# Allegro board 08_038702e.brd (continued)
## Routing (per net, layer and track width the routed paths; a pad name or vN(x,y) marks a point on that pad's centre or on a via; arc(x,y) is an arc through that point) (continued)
PS_MIO41_501_SD0_CMD: length 53.3
  TOP w0.14: U11.4 10.36,14.84 10.93,14.26 16.87,14.26 17.07,14.46 v1(17.07,14.84) ; U1.C19 v1(45.22,24.59)
  L17_SIG w0.095: v1(45.22,24.59) 45.22,24.57 44.63,23.98 43.34,23.98 40.29,27.03 33.11,27.03 32.85,27.29 32.85,27.38 32.55,27.68 32.55,27.73 32.36,27.93 32.3,27.93 31.65,28.58 31.65,30.04 31.49,30.21 25.33,30.21 24.56,29.44 24.56,22.45 21.36,19.25 21.22,19.25 19.27,17.29 19.27,16.02 19.23,15.98 19.23,14.97 18.34,14.08 17.71,14.08 17.6,14.18 17.35,14.18 17.07,14.46 v1(17.07,14.84)
PS_MIO42_501_SD0_DATA0: length 48.7
  TOP w0.14: U1.F17 v1(42.22,26.59) ; v1(10.47,16.11) 10.19,15.84 U11.6
  L17_SIG w0.095: v1(10.47,16.11) 10.72,16.36 11.61,16.36 12.5,15.48 15.04,15.48 15.29,15.73 15.29,16.49 15.8,17 16.44,17 19.27,19.83 19.27,20.12 21.07,21.93 21.36,21.93 21.88,22.45 21.88,22.73 22.07,22.93 22.36,22.93 22.88,23.45 22.88,30.81 23.32,31.25 23.36,31.25 23.56,31.45 23.56,31.49 24.06,31.99 31.42,31.99 31.88,31.53 31.88,31.45 32.07,31.25 32.16,31.25 33.49,29.91 33.97,29.91 34.17,29.71 34.17,29.23 34.48,28.93 40.36,28.93 40.56,28.73 40.56,28.45 41.07,27.93 41.36,27.93 41.56,27.73 41.56,27.44 42.22,26.78 v1(42.22,26.59)
PS_MIO43_501_SD0_DATA1: length 51.2
  TOP w0.14: v1(9.7,17.76) 9.05,17.11 U11.7 ; U1.D18 v1(44.22,25.59)
  L17_SIG w0.095: v1(9.7,17.76) 14.4,17.76 15.8,19.16 17.83,19.16 20.5,21.83 20.5,29.57 21.18,30.25 21.36,30.25 23.56,32.45 23.56,32.63 24.06,33.13 31.09,33.13 31.29,32.93 31.36,32.93 32.55,31.73 32.55,31.67 35.07,29.15 40.45,29.15 40.78,28.82 40.78,28.54 41.17,28.15 41.45,28.15 41.78,27.82 41.78,27.53 42.56,26.75 42.56,26.69 43,26.25 43.56,26.25 v1(44.22,25.59)
PS_MIO44_501_SD0_DATA2: length 50
  TOP w0.14: U1.E18 v1(43.22,25.59) ; v1(10.59,13.06) 10.32,13.34 U11.1
  L17_SIG w0.095: v1(10.59,13.06) 10.89,13.36 12.29,13.36 13.77,14.84 15.93,14.84 16.31,15.22 17.58,15.22 18.98,16.62 18.98,17.89 19.27,18.18 19.27,18.54 19.47,18.74 19.82,18.74 20.12,19.03 20.37,19.03 20.88,19.53 20.88,19.73 23.07,21.93 23.27,21.93 23.88,22.53 23.88,29.73 25.12,30.97 31.04,30.97 31.88,30.13 31.88,29.45 32.55,28.77 32.55,28.57 33.19,27.93 40.36,27.93 40.56,27.73 40.56,27.45 41.07,26.93 41.36,26.93 41.56,26.73 41.56,26.45 42.07,25.93 42.36,25.93 42.7,25.59 v1(43.22,25.59)
PS_MIO45_501_SD0_DATA3: length 52.2
  TOP w0.14: U11.3 10.34,14.34 v1(10.97,13.7) ; U1.C18 v1(45.22,25.59)
  L17_SIG w0.095: v1(45.22,25.59) 45.22,25.59 44.63,25 44.12,25 43.61,25.51 43.61,25.76 43.36,26.02 42.6,26.02 42.37,26.25 42.07,26.25 41.88,26.45 41.88,26.74 41.46,27.15 41.17,27.15 40.78,27.54 40.78,27.82 40.45,28.15 34.17,28.15 32.88,29.45 32.88,29.61 31.29,31.19 24.34,31.19 23.88,30.73 23.88,30.66 23.55,30.33 23.55,29.74 23.56,29.73 23.56,23.13 23.36,22.93 23.07,22.93 22.88,22.73 22.88,22.45 22.36,21.93 22.07,21.93 21.88,21.73 21.88,21.45 21.36,20.93 21.07,20.93 20.88,20.73 20.88,20.3 20.5,19.92 20.12,19.92 18.59,18.4 18.47,18.4 16.44,16.36 16.44,15.82 15.67,15.06 13.68,15.06 12.31,13.7 v1(10.97,13.7)
PS_MIO46_501_JX4: length 50.9
  TOP w0.14: U1.E17 v1(43.22,26.59)
  L17_SIG w0.095: v1(78.79,16.24) 78.41,16.62 77.52,16.62 77.14,17 77.14,19.03 76.76,19.41 75.87,19.41 75.49,19.03 75.49,18.02 75.11,17.63 74.47,17.63 74.09,18.02 74.09,22.84 71.68,25.25 58.38,25.25 57.84,24.71 50,24.71 47.68,27.03 43.61,27.03 43.22,26.63 v1(43.22,26.59)
  BOTTOM w0.14: JX4.92 80.46,14.57 v1(78.79,16.24)
PS_MIO47_501_JX4: length 49.1
  TOP w0.14: U1.B19 v1(46.22,24.59)
  L17_SIG w0.095: v1(46.22,24.59) 46.69,24.11 49.2,24.11 49.46,23.86 58.47,23.86 59.11,24.49 59.87,24.49 60.12,24.24 60.89,24.24 61.39,24.75 65.58,24.75 65.84,24.49 71.93,24.49 73.71,22.71 73.71,19.29 73.2,18.78 73.2,17.13 73.59,16.75 75.49,16.75 75.87,17.13 75.87,18.52 76.13,18.78 76.5,18.78 76.76,18.52 76.76,16.49 77.14,16.11 v1(77.78,16.11)
  BOTTOM w0.14: v1(77.78,16.11) 79.81,14.08 80.44,14.08 80.75,13.77 JX4.94
PS_MIO48_501_JX4: length 47.2
  TOP w0.14: U1.B21 v1(46.22,22.59)
  L6_SIG w0.095: v1(46.22,22.59) 46.72,22.08 47.8,22.08 48.06,22.33 48.31,22.33 49.2,21.44 50.44,21.44 50.45,21.45 52.33,21.45 52.34,21.44 54.28,21.44 55.04,20.68 57.33,20.68 58.09,19.92 73.84,19.92 75.87,17.89 78.54,17.89 79.05,17.38 80.32,17.38 81.46,16.24 81.46,12.94 82.98,11.41 v1(84.38,11.41)
  BOTTOM w0.14: v1(84.38,11.41) 84.42,11.37 JX4.99
PS_MIO49_501_JX4: length 51.3
  TOP w0.14: U1.A18 v1(47.22,25.59)
  L6_SIG w0.095: v1(47.22,25.59) 46.66,25.03 46.66,23.6 47.17,23.1 47.8,23.1 48.19,22.71 48.57,22.71 49.03,22.25 52.33,22.25 52.76,21.83 54.66,21.83 54.92,21.57 57.58,21.57 58.85,20.3 60.25,20.3 60.5,20.56 61.14,20.56 61.39,20.3 68,20.3 68.51,20.81 69.78,20.81 70.28,20.3 74.6,20.3 76.76,18.14 78.98,18.14 79.13,18.29 79.47,18.29 79.62,18.14 82.71,18.14 82.71,18.13 82.91,17.93 83.19,17.93 83.28,18.03 83.48,18.03 83.75,17.76 83.75,13.06 83.49,12.81 v1(83.49,11.92)
  BOTTOM w0.14: JX4.98 81.55,12.17 83.24,12.17 v1(83.49,11.92)
PS_MIO50_501_SD0_CD: length 72.7
  TOP w0.14: v1(77.9,59.16) 77.9,58.66 78.08,58.47 U5.8 ; U1.B22 v1(46.22,21.59)
  L15_SIG w0.095: v3(70.41,21.19) 70.41,22.21 73.84,25.64 73.84,31.73 70.66,34.91 70.66,37.83 72.57,39.73 72.57,50.02 73.97,51.42 73.97,52.31 75.87,54.21 76.76,54.21 78.67,56.12 78.67,58.4 v1(77.9,59.16)
  L17_SIG w0.095: v3(70.41,21.19) 69.9,20.68 65.84,20.68 65.2,20.05 61.39,20.05 58.98,22.46 49.33,22.46 49.07,22.21 46.79,22.21 46.22,21.63 v1(46.22,21.59)
PS_MIO51_501_JX4: length 49.1
  TOP w0.14: U1.B20 v1(46.22,23.59)
  L6_SIG w0.095: v1(46.22,23.59) 46.22,23.54 45.77,23.1 45.01,23.1 44.76,22.84 44.76,21.44 45.14,21.06 46.28,21.06 46.88,20.47 46.88,20.45 47.07,20.25 48.11,20.25 48.44,19.92 57.46,19.92 59.23,18.14 60.12,18.14 60.76,18.78 70.28,18.78 70.54,18.52 70.92,18.52 74.09,15.35 74.09,14.33 77.9,10.52 82.35,10.52 v1(82.73,10.9)
  BOTTOM w0.14: JX4.100 82.26,11.37 v1(82.73,10.9)
PS_MIO52_501_ETH0_MDC: length 52.2
  TOP w0.14: U1.A20 v1(47.22,23.59)
  L17_SIG w0.095: v1(25.96,2.78) 26.34,2.78 26.47,2.65 28.25,2.65 29.01,3.41 33.45,3.41 35.1,5.06 40.18,5.06 40.69,5.57 46.03,5.57 v3(46.79,6.33)
  L18_SIG w0.095: v3(46.79,6.33) 49.33,8.87 49.33,9.63 50.73,11.03 50.73,13.7 50.47,13.95 50.47,15.22 50.98,15.73 50.98,20.41 50.73,20.65 50.57,20.65 49.45,21.77 49.45,21.95 47.82,23.59 v1(47.22,23.59) ; v1(21.13,1.12) 22.79,2.78 25.3,2.78 25.31,2.77 25.59,2.77 25.6,2.78 v1(25.96,2.78)
  BOTTOM w0.14: U10.7 21.89,2.86 21.66,2.63 21.66,1.65 v1(21.13,1.12)
PS_MIO53_501_ETH0_MDIO: length 51.7
  TOP w0.14: U1.A19 v1(47.22,24.59)
  L17_SIG w0.095: v3(45.65,6.33) 45.14,5.82 40.44,5.82 40.18,5.57 32.95,5.57 31.8,4.43 31.17,4.43 30.53,3.79 28.63,3.79 27.99,4.43 v1(27.36,4.43)
  L18_SIG w0.095: v3(45.65,6.33) 46.92,7.6 47.3,7.6 48.06,8.36 48.06,10.65 48.95,11.54 48.95,13.57 49.33,13.95 49.33,17.63 49.2,17.76 49.2,21.19 47.3,23.1 47.04,23.1 46.79,23.35 46.79,24.16 v1(47.22,24.59) ; v1(21.01,1.63) 23.42,4.05 26.98,4.05 v1(27.36,4.43)
  BOTTOM w0.14: R11.2 27.74,4.05 v1(27.36,4.43) ; v1(21.01,1.63) 21.01,2.39 21.39,2.78 U10.8
PWR_ENABLE: length 135.2
  TOP w0.14: v1(31.93,57.64) 31.55,57.26 30.41,57.26 29.8,56.66 29.8,56.54 29.45,56.19 R56.2 ; v2(58.35,11.28) 58.47,11.28 58.75,11.01 U4.12 ; U18.20 25.57,5.71 25.83,5.44 25.83,4.05 25.45,3.66 v1(25.45,3.11)
  L2_GND w0.203: v2(58.35,11.28) v3(57.96,11.28)
  L3_SIG w0.095: v3(57.96,11.28) 58.28,11.6 58.41,11.6 58.6,11.41 59.11,11.41 59.38,11.69 59.38,11.69 59.74,12.05 59.74,12.9 60.12,13.28 60.12,14.33 59.28,15.18 59.28,17.29 60.38,18.4 60.38,19.03 60.12,19.29 60.12,22.33 59,23.46 59,24.89 59.36,25.25 59.36,29.06 59.23,29.19 v1(59.23,30.21)
  L7_SIG w0.095: v3(57.96,11.28) 57.08,11.28 56.06,10.27 56.06,3.03 53.9,0.87 35.36,0.87 34.09,2.14 34.09,4.43 33.07,5.44 31.29,5.44 30.66,4.81 29.64,4.81 27.27,2.44 25.79,2.44 25.45,2.78 v1(25.45,3.11)
  L17_SIG w0.095: v3(49.07,30.84) 53.93,30.84 54.14,31.06 54.42,31.06 54.63,30.84 57.46,30.84 58.43,29.87 58.87,29.87 59.21,30.21 v1(59.23,30.21)
  L18_SIG w0.095: v3(49.07,30.84) 48.82,31.1 43.99,31.1 43.61,31.48 43.61,34.78 43.36,35.03 42.09,35.03 41.71,35.41 41.71,43.92 41.33,44.3 41.33,46.84 41.84,47.35 41.84,52.56 40.69,53.7 40.69,54.46 41.33,55.1 41.33,57 39.04,59.29 32.69,59.29 31.93,58.53 v1(31.93,57.64)
  BOTTOM w0.14: JX1.5 32.73,56.84 v1(31.93,57.64)
PWR_GD: length 172
  TOP w0.203: U7.37 v1(5.91,42.03)
  TOP w0.254: v1(42.34,53.83) 41.96,53.44 U9.7
  TOP w0.305: U19.5 71.13,7.77 v1(71.55,7.35) ; R306.1 v1(72.82,7.35)
  TOP w0.381: U20.5 80.91,7.77 v1(81.21,7.47)
  L9_POWER w0.508: v1(81.21,7.47) 80.82,7.09 76.89,7.09 75.02,5.23 74.31,5.23 72.82,6.71 v1(72.82,7.35) v1(71.55,7.35)
  L17_SIG w0.508: v1(81.21,7.47) 81.84,6.84 86.16,6.84 88.57,9.25 88.57,34.4 89.84,35.67 89.84,43.8 88.57,45.07 88.57,51.04 84.25,55.35 78.03,55.35 77.9,55.23 73.59,55.23 73.08,54.72 71.43,54.72 70.66,55.48 43.11,55.48 42.34,54.72 ; v1(5.91,42.03) 6.53,42.65 6.53,44.05 5.39,45.19 5.39,51.42 11.61,57.64 14.4,57.64 15.29,58.53 21.64,58.53 22.59,57.58 25.78,57.58 26.34,58.15 28.37,58.15 29.26,59.04 35.36,59.04 36.5,57.89 36.5,56.24 37.26,55.48 41.58,55.48 42.34,54.72 ; 42.34,54.72 v1(42.34,53.83)
PWR_GD_1.35V: length 86.5
  TOP w0.102: v1(25.92,3.32) 25.92,3.37 26.09,3.54 26.09,5.95 25.83,6.21 U18.21
  TOP w0.203: U1.C23 v1(45.22,20.59)
  TOP w0.254: R3.2 41.58,4.3 v1(41.07,4.81) ; v1(40.57,4.81) 40.31,4.81 39.93,5.19 SW1.1A
  TOP w0.305: U4.2 62.42,8.12 62.59,7.96 62.65,7.96 v1(62.68,7.92) ; v2(62.28,10.65) 62.28,10.27 62.14,10.12 U4.6
  TOP w0.508: SW1.1B SW1.1A
  L2_GND w0.305: v2(62.28,10.65) v3(62.79,10.65)
  L3_SIG w0.254: v1(61.65,13.44) 61.9,13.44 62.54,12.81 62.54,10.9 v3(62.79,10.65) 62.68,10.54 v1(62.68,7.92) 61.84,7.92 60.5,6.59 59.36,6.59 55.93,3.16 54.66,3.16 53.68,4.14 50.63,4.14 49.67,5.1 44.92,5.1 43.81,3.99 41.25,3.99 41.07,4.17 v1(41.07,4.81) v1(40.57,4.81)
  L11_POWER w0.254: v1(61.65,13.44) 60.38,14.71 55.55,14.71 53.39,16.87 53.39,21.83 52.63,22.59 49.46,22.59 47.93,21.06 45.69,21.06 v1(45.22,20.59)
  L14_SIG w0.254: v1(25.92,3.32) 26.3,3.32 26.72,2.9 30.41,2.9 31.42,3.92 34.34,3.92 35.23,4.81 v1(40.57,4.81) v1(41.07,4.81)
  BOTTOM w0.305: R29.2 61.01,13.7 61.06,13.65 61.31,13.65 61.52,13.44 v1(61.65,13.44)
REF_IN_OUT: length 5.3
  TOP w0.14: U7.13 v1(14.13,41.53) 14.13,41.66 13.76,42.03 U7.14
  BOTTOM w0.14: C202.1 14.53,40.75 14.28,41 14.28,41.38 v1(14.13,41.53)
RX1A_N: length 2.5
  TOP w0.089: U17.M2 68.96,34.09 69.09,34.22 69.09,34.73 70.03,35.67 70.03,35.8 C8.2
RX1A_P: length 2.5
  TOP w0.089: U17.M1 69.48,34.09 69.31,34.27 69.31,34.64 70.11,35.44 C9.2
RX1B_N: length 3.6
  TOP w0.089: U17.J1 69.89,31.4 70.06,31.4 70.18,31.52 70.2,31.52 70.28,31.6 70.28,32.75 70.41,32.87 70.41,33.13 70.66,33.38 71.11,33.38 C51.2
RX1B_P: length 3.6
  TOP w0.089: U17.H1 69.89,31.19 70.15,31.19 70.27,31.31 70.29,31.31 70.5,31.51 70.5,32.66 70.63,32.78 70.63,33.04 70.75,33.17 71.06,33.17 C52.2
RX2A_N: length 2.9
  TOP w0.089: U17.A1 69.33,25.29 69.29,25.26 69.29,25.13 69.36,25.07 69.36,24.91 69.52,24.75 70.79,24.75 70.92,24.62 70.93,24.63 C10.2
RX2A_P: length 2.8
  TOP w0.089: C11.2 70.82,24.4 70.83,24.4 70.7,24.53 69.43,24.53 69.14,24.82 69.14,24.98 68.83,25.29 U17.A2
RX2B_N: length 2.8
  TOP w0.089: C53.2 71.32,27.88 70.88,27.88 70.63,28.14 70.63,28.65 70.27,29 69.89,29 U17.F1
RX2B_P: length 2.9
  TOP w0.089: U17.E1 69.89,28.79 70.18,28.79 70.41,28.56 70.41,28.05 70.79,27.67 71.22,27.67 C56.2
S_IN_N: length 57.1
  L17_SIG w0.089: v1(6.53,7.28) 6.74,7.49 9.18,7.49 11.61,5.06 18.85,5.06 19.61,4.3 19.61,3.66 20.25,3.03 21.13,3.03 22.28,4.17 23.8,4.17 24.06,3.92 24.06,3.41 24.44,3.03 24.44,2.39 24.33,2.29 v1(24.33,2.01)
  BOTTOM w0.089: U10.2 24.39,2.6 24.53,2.46 24.53,2.22 v1(24.33,2.01) ; v1(6.53,7.28) 6.29,7.51 5.48,7.51 4.62,8.36 2.59,8.36 1.58,9.38 1.58,23.1 0.9,23.77 0.9,32.2 2.27,33.57 3.54,33.57 3.79,33.81 JP2.3
S_IN_P: length 57.1
  L17_SIG w0.089: v1(6.53,7.96) 6.74,7.75 9.28,7.75 11.71,5.32 18.95,5.32 19.86,4.4 19.86,3.77 20.35,3.28 21.03,3.28 22.17,4.43 23.91,4.43 24.31,4.02 24.31,3.52 24.69,3.13 24.69,2.97 24.82,2.84 24.82,2.65 24.69,2.52 24.69,2.14 24.82,2.01 v1(25.01,2.01)
  BOTTOM w0.089: U10.1 24.89,2.6 24.75,2.46 24.75,2.28 v1(25.01,2.01) ; JP1.3 3.79,33.22 3.65,33.36 2.36,33.36 1.11,32.11 1.11,23.86 1.79,23.19 1.79,9.47 2.68,8.58 4.71,8.58 5.56,7.73 6.29,7.73 v1(6.53,7.96)
S_OUT_N: length 56.4
  L7_SIG w0.089: v1(17.96,32.49) 17.96,32.37 17.71,32.11 16.94,32.11 15.42,33.64 9.32,33.64 7.42,31.73 7.42,29.06 9.2,27.29 11.86,27.29 13.96,25.19 13.96,21.45 13.69,21.18 13.69,20.69 14.15,20.23 14.15,19.67 14.53,19.29 14.53,18.78 13.54,17.79 13.54,17.22 13.43,17.12 13.43,16.12 13.54,16.01 13.54,13.93 15.04,12.43 15.04,11.03 15.8,10.27 16.69,10.27 17.71,9.25 17.71,6.33 19.61,4.43 19.61,3.66 20.84,2.44 22.89,2.44 23.04,2.29 23.04,2.01 v1(22.79,1.76)
  BOTTOM w0.089: v1(22.79,1.76) 23.03,2.01 23.03,2.46 22.89,2.6 U10.5 ; JP4.3 17.15,32.29 17.39,32.05 17.51,32.05 v1(17.96,32.49)
S_OUT_P: length 56.4
  L7_SIG w0.089: v1(17.96,31.73) 17.83,31.86 16.84,31.86 15.31,33.38 9.43,33.38 7.67,31.63 7.67,29.17 9.3,27.54 11.97,27.54 14.21,25.3 14.21,21.35 13.94,21.08 13.94,20.8 14.4,20.33 14.4,19.77 14.78,19.39 14.78,18.67 13.79,17.68 13.79,17.12 13.69,17.01 13.69,16.23 13.79,16.12 13.79,14.03 15.29,12.53 15.29,11.14 15.91,10.52 16.79,10.52 17.96,9.36 17.96,6.44 19.86,4.53 19.86,3.77 20.94,2.69 22.99,2.69 23.29,2.39 23.29,2.01 v1(23.55,1.76)
  BOTTOM w0.089: JP3.3 17.07,30.79 17.07,31.6 17.3,31.83 17.6,31.83 17.79,32.02 17.92,32.02 17.98,31.96 17.98,31.76 v1(17.96,31.73) ; U10.4 23.39,2.6 23.25,2.46 23.25,2.06 v1(23.55,1.76)
SCL: length 69.5
  TOP w0.14: U1.AF24 v1(21.22,19.59)
  L14_SIG w0.095: v1(37.85,8.52) 37.7,8.36 37.52,8.36 36.88,7.73 36.88,7.6 35.96,6.68 29.36,6.68 28.75,6.08 27.36,6.08 27.1,6.33 26.34,6.33 24.69,4.68 22.02,4.68 21.32,5.38 20.82,5.38 20.37,5.82 19.86,5.82 19.48,5.44 18.72,5.44 17.71,6.46 17.71,10.9 17.03,11.58 15.63,11.58 15.29,11.92 15.29,14.08 16.44,15.22 17.58,15.22 17.83,15.48 17.83,15.98 17.32,16.49 17.32,17.38 17.71,17.76 20.5,17.76 20.75,18.02 21.39,18.02 21.64,18.27 21.64,18.78 21.22,19.2 v1(21.22,19.59) 20.17,19.59 19.86,19.29 18.21,19.29 16.94,20.56 14.15,20.56 12.75,21.95 11.1,21.95 9.96,23.1 7.49,23.1 4.31,19.92 4.31,19.41 v1(4.24,19.34)
  BOTTOM w0.14: R58.2 v1(4.24,19.34) 4.31,19.41 U21.2 ; JX2.17 37.53,9.12 37.77,8.87 37.77,8.59 v1(37.85,8.52)
SCL_ADM1166: length 182.3
  TOP w0.14: U7.35 v1(5.9,43.03)
  L4_SIG w0.095: v1(4.23,42.78) 4.75,42.78 5.01,43.03 5.89,43.03 v1(5.9,43.03) 6.53,42.4 6.53,41.51 4.88,39.86 4.88,32.49 5.77,31.6 5.77,25.38 v1(6.15,25)
  L14_SIG w0.095: v1(6.15,25) 6.78,25 7.29,25.51 11.61,25.51 12.63,24.49 16.18,24.49 18.72,21.95 21.37,21.95 22.07,21.25 22.22,21.25 22.79,20.68 22.79,19.54 22.88,19.45 23.07,19.25 23.58,19.25 23.88,18.96 23.88,16.1 24.82,15.15 24.82,14.33 25.96,13.19 30.53,13.19 32.06,11.67 36.88,11.67 37.39,12.17 v3(37.39,12.55)
  L17_SIG w0.095: v3(37.39,12.55) 39.42,10.52 48.19,10.52 49.58,9.13 50.34,9.13 52.12,7.35 63.93,7.35 65.2,6.08 72.44,6.08 72.82,5.7 75.49,5.7 76.38,6.59 78.54,6.59 82.09,10.14 85.02,10.14 86.29,11.41 86.29,33.26 88.32,35.29 88.32,41.89 v1(87.43,42.78) 85.9,41.26 85.9,40.37 85.02,39.48 83.24,39.48 80.95,41.76 80.95,43.29 77.78,46.46 v3(77.78,47.61)
  L19_GND w0.203: v4(77.27,47.61) v3(77.78,47.61)
  BOTTOM w0.14: R51.2 v1(4.23,42.78) ; v1(6.15,25) 5.64,24.49 4.62,24.49 4.31,24.8 U21.7 ; P1.A4 v1(87.43,42.78) ; U24.15 77.13,47.46 v4(77.27,47.61)
  BOTTOM w0.381: P1.B4 94.41,42.78 93.78,42.15 91.87,42.15 91.24,42.78 P1.A4
SD_SEL: length 147.5
  TOP w0.14: U5.5 v2(79.68,57.51) ; U11.24 9.05,12.66 9.2,12.81 10.21,12.81 v1(10.59,12.43) ; S1.2 v1(2.89,11.71)
  L2_GND w0.305: v2(79.68,57.51) v3(79.17,57.51)
  L14_SIG w0.095: v3(79.17,57.51) 79.81,58.15 79.81,60.43 79.05,61.2 51.11,61.2 50.73,60.81 48.69,60.81 48.31,60.43 47.1,60.43 47.08,60.41 46.75,60.41 46.73,60.43 44.38,60.43 43.93,60.88 33.39,60.88 31.93,59.42 28.12,59.42 27.61,59.93 22.28,59.93 20.75,58.4 20.75,54.97 19.1,53.32 15.67,53.32 12.75,50.4 12.75,46.84 11.61,45.7 9.2,45.7 7.67,44.18 4.62,44.18 2.85,42.4 2.85,41.64 0.56,39.35 0.56,16.24 3.61,13.19 9.83,13.19 v1(10.59,12.43)
  L17_SIG w0.095: v1(2.89,11.71) 5.47,11.71 5.77,11.41 8.05,11.41 9.32,12.68 10.34,12.68 v1(10.59,12.43)
  BOTTOM w0.14: v1(11.99,9.63) 11.99,10.14 10.59,11.54 v1(10.59,12.43)
SDA: length 69
  TOP w0.14: U1.AF25 v1(21.22,18.59)
  L14_SIG w0.095: v1(39.14,9) 39.14,8.97 38.79,8.62 38.79,7.98 38.15,7.35 37.01,7.35 36.12,6.46 29.9,6.46 29.26,5.82 27.61,5.82 27.36,5.57 25.96,5.57 24.82,4.43 21.9,4.43 21.39,4.93 20.2,4.93 19.95,5.19 18.47,5.19 17.32,6.33 17.32,10.78 16.74,11.36 15.47,11.36 15.04,11.79 15.04,14.21 16.44,15.6 16.44,16.24 17.07,16.87 17.07,17.63 17.45,18.02 20.37,18.02 20.59,18.24 21.13,18.24 21.22,18.32 v1(21.22,18.59) 20.31,18.59 19.91,18.99 17.11,18.99 16.56,19.54 14.4,19.54 13.64,20.3 5.77,20.3 4.37,18.9 3.86,18.9 3.48,19.29 v1(3.1,19.29)
  BOTTOM w0.14: v1(39.14,9) 38.58,9 38.33,9.25 JX2.19 ; U21.3 3.66,19.85 v1(3.1,19.29) 2.59,19.29 R57.2
SDA_ADM1166: length 179.8
  TOP w0.14: U7.36 v1(5.26,42.53)
  L4_SIG w0.095: v1(6.15,23.98) 5.39,24.75 5.39,31.22 4.5,32.11 4.5,40.62 4.24,40.88 v1(4.24,42.02) 4.75,42.02 v1(5.26,42.53)
  L14_SIG w0.095: v1(6.15,23.98) 6.66,24.49 11.1,24.49 11.74,23.86 15.17,23.86 16.56,22.46 16.94,22.46 18.34,21.06 21.39,21.06 21.77,20.68 21.77,19.41 22.15,19.03 22.98,19.03 22.98,19.03 23.29,19.03 23.55,18.77 23.55,17.45 23.55,17.44 23.55,16.11 23.93,15.73 23.93,13.95 25.96,11.92 29.9,11.92 30.53,11.28 37.01,11.28 38.15,12.43 v3(38.15,12.81)
  L17_SIG w0.095: v3(76.13,47.86) 76.13,44.69 79.43,41.38 80.32,41.38 82.73,38.97 85.9,38.97 v1(87.68,37.19) 85.9,35.41 85.9,11.67 84.63,10.4 81.97,10.4 78.54,6.97 72.57,6.97 72.19,6.59 68.38,6.59 66.47,8.49 64.95,8.49 63.45,9.99 56.29,9.99 55.42,9.13 51.23,9.13 50.85,9.51 49.92,9.51 48.4,11.03 39.93,11.03 v3(38.15,12.81)
  L19_GND w0.203: v3(76.13,47.86) 76.39,47.6 v4(76.63,47.6)
  BOTTOM w0.14: v1(6.15,23.98) 4.24,23.98 3.66,24.56 U21.6 ; P1.A3 88.95,40.24 87.94,39.22 87.94,37.45 v1(87.68,37.19) ; R52.2 v1(4.24,42.02) ; U24.14 v4(76.63,47.6)
  BOTTOM w0.381: P1.A3 P1.B3
SDIO_CLKB0: length 26.1
  TOP w0.14: v1(1.45,28.81) 2.08,28.81 2.54,28.36 J3.5 ; U11.19 6.55,12.19 v1(6.15,11.79)
  L3_SIG w0.095: v1(1.45,28.81) 1.96,28.81 2.37,28.4 2.37,28.34 4.12,26.59 4.12,20.81 4.75,20.17 4.75,18.9 4.12,18.27 4.12,16.87 3.61,16.36 2.72,16.36 2.08,15.73 2.08,15.35 1.7,14.97 1.7,14.71 4.62,11.79 v1(6.15,11.79)
SDIO_CLKB1: length 17
  TOP w0.14: v1(5.64,17) 5.04,16.4 5.04,16.2 5.41,15.84 U11.13
  L3_SIG w0.095: v1(5.64,17) 7.29,17 7.93,17.63 7.93,26.65 v1(9.45,28.17)
  BOTTOM w0.14: JX3.43 v1(9.45,28.17)
SDIO_CMDB0: length 22.2
  TOP w0.14: U11.20 7.05,12.06 v1(5.89,10.9) ; J3.3 v1(1.85,26.16)
  L3_SIG w0.095: v1(5.89,10.9) 5.13,10.9 1.07,14.97 1.07,18.52 1.45,18.9 1.45,25.76 v1(1.85,26.16)
  BOTTOM w0.14: v1(5.89,10.9) R109.2
SDIO_CMDB1: length 13.7
  TOP w0.14: v1(5.77,17.76) 6.55,16.98 U11.12
  L15_SIG w0.095: v1(5.77,17.76) 6.28,18.27 8.18,18.27 10.97,21.06 10.97,22.08 10.59,22.46 v1(10.59,23.35)
  BOTTOM w0.14: JX3.34 11.41,24.17 10.8,23.56 10.8,23.56 v1(10.59,23.35) ; v1(5.77,17.76) 4.88,17.76
SDIO_DAT0B0: length 22.4
  TOP w0.14: J3.7 v1(1.99,30.56) ; v1(4.62,12.81) 5.15,13.34 U11.18
  L15_SIG w0.095: v1(1.99,30.56) 1.93,30.56 0.94,29.57 0.94,22.84 2.34,21.44 2.34,19.03 3.03,18.34 3.03,16.94 3.99,15.98 3.99,13.44 v1(4.62,12.81)
SDIO_DAT0B1: length 14.5
  TOP w0.14: U11.14 v1(5.14,15.34)
  L3_SIG w0.095: v1(5.14,15.34) 5.14,17.65 5.77,18.27 7.04,18.27 7.55,18.78 7.55,25.02 v1(6.79,25.77)
  BOTTOM w0.14: JX3.37 v1(6.79,25.77)
SDIO_DAT1B0: length 21.8
  TOP w0.14: J3.8 v1(2.01,31.66) ; U11.16 v1(5.14,14.34)
  L3_SIG w0.095: v1(5.14,14.34) 5.13,14.33 4.37,14.33 3.99,14.71 3.99,15.98 4.62,16.62 4.62,18.4 5.01,18.78 5.01,22.71 4.37,23.35 4.37,26.65 2.59,28.43 2.59,31.1 2.03,31.66 v1(2.01,31.66)
SDIO_DAT1B1: length 19.2
  TOP w0.14: U11.15 v1(4.5,14.84)
  L3_SIG w0.095: v1(10.97,24.97) 10.97,25.13 10.47,25.64 9.45,25.64 8.94,25.13 8.94,16.62 7.16,14.84 v1(4.5,14.84)
  BOTTOM w0.14: JX3.36 v1(10.97,24.97)
SDIO_DAT2B0: length 20.5
  TOP w0.14: J3.1 v1(1.86,23.96) ; U11.23 8.55,11.93 v1(9.83,10.65)
  L15_SIG w0.095: v1(9.83,10.65) 9.32,11.16 9.32,12.43 5.75,16 5.74,16 4.88,16.86 4.88,20.43 1.86,23.45 v1(1.86,23.96)
SDIO_DAT2B1: length 14.2
  TOP w0.14: v1(6.66,19.41) 8.43,19.41 8.94,18.9 8.94,17.63 8.55,17.24 U11.8
  L3_SIG w0.095: v1(6.66,19.41) 6.66,19.98 6.68,20.01 6.68,20.66 5.81,21.53 5.81,25.55 v1(6.83,26.57)
  BOTTOM w0.14: JX3.39 v1(6.83,26.57)
SDIO_DAT3B0: length 21.5
  TOP w0.14: v1(9.07,10.65) 8.05,11.67 U11.22 ; J3.2 v1(1.89,25.06)
  L15_SIG w0.095: v1(9.07,10.65) 9.07,12.3 3.86,17.51 3.86,20.56 1.45,22.97 1.45,24.62 v1(1.89,25.06)
SDIO_DAT3B1: length 13.1
  TOP w0.14: v1(6.66,18.65) 7.04,18.65 7.55,18.14 U11.10
  L15_SIG w0.095: v1(6.66,18.65) 7.55,19.54 7.55,19.79 10.09,22.33 10.09,24.75 v1(10.34,25)
  BOTTOM w0.14: JX3.38 11.11,25.77 v1(10.34,25)
SW1: length 5.3
  TOP w0.254: v1(56.95,8.87) 57.16,9.09 57.38,9.09 57.41,9.12 U4.15
  TOP w0.508: v1(55.04,9.51) 55.04,11.05 L5.1
  L3_SIG w0.508: v1(56.95,8.87) 56.06,8.87 55.42,9.51 v1(55.04,9.51)
SW2: length 2.2
  TOP w0.305: 63.04,9.12 v2(62.28,9.12) U4.4
  TOP w0.406: L6.1 61.67,12.32 61.9,12.55 v1(62.03,12.55)
  vias: v1(61.65,12.55) v1(61.77,12.94) v2(62.54,9.13) v2(62.79,9.13) v2(63.04,9.13)
SW3: length 5.9
  TOP w0.254: U4.20 59.25,6.34 v2(59.11,6.2)
  L2_GND w0.381: v2(59.11,6.2) v3(59.49,5.82)
  L3_SIG w0.508: v3(59.49,5.82) 61.01,5.82 62.05,4.79 v1(63.19,4.79) v1(63.68,4.79)
TX1A_N: length 5.1
  TOP w0.089: C25.1 66.73,35.54 v1(66.85,35.41) 66.96,35.31 66.96,35.19 66.85,35.08 64.68,35.08 64.61,35 64.4,34.73 64.4,34.39 U17.M8
  BOTTOM w0.089: v1(66.85,35.41) 66.25,36.02 L8.2
TX1A_P: length 5.2
  TOP w0.089: U17.M7 64.62,34.27 64.62,34.65 64.78,34.87 66.94,34.87 67.27,35.19 67.27,35.32 v1(67.36,35.41) 67.49,35.54 C26.1
  BOTTOM w0.089: L9.2 67.97,36.02 v1(67.36,35.41)
TX1B_N: length 6.7
  TOP w0.089: U17.M10 62.66,34.36 62.66,34.4 62.5,34.56 62.07,34.56 61.47,35.16 v1(61.29,35.16) 61.27,35.18 C29.1
  BOTTOM w0.089: v1(61.29,35.16) 61.52,35.4 61.52,36.68 62.11,37.28 62.11,37.96 62.02,38.05 L1.2
TX1B_P: length 6.7
  TOP w0.089: C30.1 62.03,35.22 v1(61.97,35.16) 61.97,34.96 62.16,34.78 62.59,34.78 62.88,34.49 62.88,34.04 62.9,34.02 63.12,34.02 U17.M9
  BOTTOM w0.089: v1(61.97,35.16) 61.74,35.4 61.74,36.59 62.33,37.19 62.33,37.96 62.42,38.05 L2.2
TX2A_N: length 7.1
  TOP w0.089: U17.A7 64.7,25.19 64.7,24.29 65.04,23.95 65.8,23.95 65.93,23.82 66.46,23.82 v1(66.49,23.84) 66.73,23.6 C32.1
  BOTTOM w0.089: v1(66.49,23.84) 66.49,22.32 67.33,21.47 L10.2
TX2A_P: length 6.9
  TOP w0.089: U17.A8 64.28,25.29 64.48,25.09 64.48,24.2 64.95,23.73 65.71,23.73 66.01,23.43 v1(66.02,23.43) 66.58,23.43 66.73,23.29 C33.1
  BOTTOM w0.089: L11.2 65.36,21.47 66.27,22.39 66.27,23.18 v1(66.02,23.43)
TX2B_N: length 14.7
  TOP w0.089: v1(63.42,24.24) 63.36,24.17 C34.1 63.11,24.17 62.92,24.37 62.92,25.01 U17.A9
  BOTTOM w0.089: L3.2 72.79,19.57 72.06,20.3 71.84,20.3 71.52,20.62 71.52,21.41 69.61,23.31 68.29,23.31 67.24,24.37 66.75,24.37 66.72,24.39 66.26,24.39 66.24,24.37 65.67,24.37 64.73,23.44 64.73,23.44 64.61,23.31 64.02,23.31 63.42,23.91 v1(63.42,24.24)
TX2B_P: length 14.7
  TOP w0.089: v1(62.41,24.24) C35.1 62.7,24.34 62.7,24.99 U17.A10
  BOTTOM w0.089: v1(62.41,24.24) 63.93,23.1 64.48,23.1 64.69,23.1 65.76,24.16 66.33,24.16 66.35,24.18 66.63,24.18 66.66,24.15 67.15,24.15 68.2,23.1 69.52,23.1 71.3,21.32 71.3,20.17 70.57,19.44 L4.2
TX_MON1: length 6.5
  TOP w0.14: U17.M5 66.8,34.49 67.14,34.49 67.46,34.82 67.78,34.82 70.22,37.26 C6.2
TX_MON2: length 2.8
  TOP w0.14: C7.2 68.51,24.49 67.24,24.49 66.43,25.29 U17.A5
TX_VCO_1P1V_SUPPLY: length 2.2
  TOP w0.14: U17.B11 v6(61.2,25.69) U17.A11
  BOTTOM w0.14: C104.2 61.08,25.81 v6(61.2,25.69) 61.2,25.45 61.52,25.13 R123.1
UNNAMED_2_CAP_I87_N1: length 1.9
  BOTTOM w0.14: U10.41 24.44,11.09 24.44,11.79 23.93,12.3 C242.1
UNNAMED_2_CAP_I87_N2: length 1.7
  BOTTOM w0.14: C242.2 22.39,12.42 U10.37
UNNAMED_2_CAP_I88_N1: length 23.8
  TOP w0.14: Y2.3 35.78,13.66 v1(36.63,12.81)
  L3_SIG w0.095: v1(20.63,11.79) 21.05,12.21 22.4,12.21 22.62,12.43 24.18,12.43 24.4,12.21 27.57,12.21 27.87,11.92 29.9,11.92 30.53,11.28 34.34,11.28 35.87,12.81 v1(36.63,12.81)
  BOTTOM w0.14: U10.34 20.89,11.53 v1(20.63,11.79) 19.32,13.1 C60.1
UNNAMED_2_CAP_I90_N1: length 22.5
  TOP w0.14: v1(30.36,12.81) 31.2,11.96 Y2.1 ; v1(13.77,10.78) 13.13,10.78 12.84,11.07 C59.1
  L15_SIG w0.095: v1(13.77,10.78) 14.91,10.78 15.55,11.41 16.92,11.41 17.28,11.78 17.28,12.13 17.71,12.55 19.23,12.55 v1(19.99,11.79)
  L18_SIG w0.095: v1(19.99,11.79) 20.5,12.3 24.31,12.3 24.44,12.17 29.72,12.17 v1(30.36,12.81)
  BOTTOM w0.14: v1(19.99,11.79) 20.39,11.39 U10.33
UNNAMED_2_DIO6PV8_I47_REF1: length 2.1
  BOTTOM w0.14: v1(15.55,54.46) 15.55,54.72 15.27,54.99 15.01,54.99 14.9,55.1 R178.2
UNNAMED_2_IC88E151X_I86_CONFIG: length 2.3
  BOTTOM w0.14: R12.2 16.05,2.78 17.12,3.84 U10.15
UNNAMED_2_IC88E151X_I86_RSET: length 3.5
  BOTTOM w0.14: U10.30 18.89,11.49 18.09,12.3 16.94,12.3 R50.1
UNNAMED_2_ICUSB3320C_I42_RBIAS: length 2.3
  TOP w0.14: U15.24 19.13,51.19 R176.1
UNNAMED_2_ICUSB3320C_I42_REFCLK: length 4
  TOP w0.14: U15.26 21.66,49.91 v1(21.39,49.64)
  BOTTOM w0.14: R175.1 21.39,51.2 v1(21.39,49.64)
UNNAMED_2_ICXC7Z035_I20_PSMIOVR: length 18
  TOP w0.14: R194.2 42.98,15.6 v1(43.74,16.36) 44.5,15.6 R191.1 ; U1.H18 v1(40.22,25.59)
  BOTTOM w0.14: v1(43.74,16.36) 42.58,17.53 42.58,17.74 42.37,17.95 42.15,17.95 41.58,18.53 41.58,26.91 41.33,27.16 41.07,27.16 40.69,26.78 40.69,26.07 v1(40.22,25.59)
UNNAMED_2_RES_I50_N2: length 6.1
  TOP w0.14: v1(21.39,56.24) 20.25,56.24 19.86,56.62 18.84,56.62 Y3.3
  BOTTOM w0.14: R175.2 22.32,53.92 21.39,54.85 v1(21.39,56.24)
UNNAMED_2_RES_I105_N1: length 2.3
  TOP w0.14: R18.1 2.59,53.19 3.23,52.56 Q4.3
UNNAMED_2_RES_I108_N2: length 8.1
  TOP w0.14: Q4.1 6.22,51.62 7.24,52.64 7.24,55.3 R16.2 9.07,57.13 Q2.3
UNNAMED_2_RES_I112_N1: length 2.1
  TOP w0.14: R17.1 39.04,13.32 Q3.3
UNNAMED_2_RES_I114_N2: length 6.3
  TOP w0.14: Q3.1 37.7,9.13 Q1.3 35.99,9.02 35.99,8.24 34.98,7.22 34.85,7.22 R15.2
UNNAMED_3_ADM1166_I104_A0: length 4.6
  TOP w0.14: U7.33 4.52,44.03 4.37,44.18 3.67,44.18 R38.1 R30.2
UNNAMED_3_ADM1166_I104_A1: length 4.6
  TOP w0.14: R39.2 R40.1 3.56,43.27 4.86,43.27 5.12,43.53 U7.34
UNNAMED_3_ADM1166_I104_DAC1: length 3.2
  TOP w0.14: U7.15 15.03,42.53 v1(15.16,42.4)
  BOTTOM w0.14: R41.1 v1(15.16,42.4)
UNNAMED_3_ADM1166_I104_DAC2: length 4
  TOP w0.14: R42.1 15.17,44.56 14.81,44.56 14.28,44.02 14.28,43.55 13.76,43.03 U7.16
UNNAMED_3_ADM1166_I104_DAC3: length 7.3
  TOP w0.14: v1(13.9,43.92) 13.5,43.53 U7.17
  BOTTOM w0.14: v1(13.9,43.92) 15.04,45.07 15.04,46.59 15.67,47.23 v1(15.67,48.5) R44.1
UNNAMED_3_ADM1166_I104_DAC4: length 15.3
  TOP w0.14: U7.18 13.37,44.03 v1(13.9,44.56)
  L3_SIG w0.095: v1(13.9,44.56) 14.02,44.69 14.28,44.69 14.66,45.07 14.66,45.7 14.02,46.34 14.02,48.59 14.27,48.83 14.27,49.11 13.94,49.44 13.94,51.58 16.69,54.34 v1(17.32,54.34)
  BOTTOM w0.14: v1(17.32,54.34) 17.32,54.08 R45.1
UNNAMED_3_ADM1166_I104_VCCP: length 3.7
  TOP w0.14: U7.32 5.5,44.53 C204.1
UNNAMED_3_ICN25Q256AV2_I216_RES: length 8.2
  TOP w0.14: v1(68.89,48.5) 68.89,51.67 69.15,51.94 69.15,53.84 69.23,53.92 69.23,55.23 U13.A4
  BOTTOM w0.14: R19.2 v1(68.89,48.5)
UNNAMED_3_ICXC7Z035_I94_PSCLK50: length 9.4
  TOP w0.14: U1.B24 v1(46.22,19.59) ; R114.2 v1(46.03,12.94)
  L18_SIG w0.095: v1(46.03,12.94) 45.65,13.32 45.65,19.02 v1(46.22,19.59)
UNNAMED_3_ICXC7Z035_I94_PSMIO12: length 7.7
  TOP w0.14: U1.A23 v1(47.22,20.59)
  BOTTOM w0.14: R60.1 45.32,16.14 45.77,16.59 45.77,17.89 46.03,18.14 47.42,18.14 47.68,18.4 47.68,20.13 v1(47.22,20.59)
UNNAMED_3_RES_I9_N1: length 2.5
  TOP w0.14: Y1.3 46.14,7.95 45.91,8.18 45.91,9.43 R114.1
UNNAMED_3_RES_I30_N2: length 19.3
  TOP w0.14: v1(54.66,57.39) 54.1,57.39 54.03,57.46 53.8,57.46 53.77,57.43 53.6,57.43 53.55,57.39 53.27,57.39 52.88,57 S3.2
  L6_SIG w0.095: v1(69.14,59.29) 64.7,59.29 63.93,58.53 58.85,58.53 58.6,58.78 56.06,58.78 v1(54.66,57.39)
  BOTTOM w0.14: R121.2 69.9,58.53 v1(69.14,59.29)
UNNAMED_3_RES_I33_N2: length 18.6
  TOP w0.14: v1(48.19,57.89) 48.19,57.64 48.29,57.54 48.29,56.98 47.72,56.41 S4.2
  BOTTOM w0.14: v1(48.19,57.89) 48.19,57.64 48.44,57.39 51.23,57.39 51.8,57.95 51.8,57.95 52.19,58.34 52.19,58.34 52.5,58.66 56.82,58.66 58.47,57 61.65,57 62.16,57.51 62.28,57.51
UNNAMED_3_RES_I237_N2: length 2.9
  TOP w0.14: v1(48.31,4.17) 48.31,4.55 47.58,5.29 Y1.1
  BOTTOM w0.14: v1(48.31,4.17) 48.12,4.36 R77.1 47.74,4.55 R76.2
UNNAMED_4_CN100PODDEVEN_I16_N4: length 6.8
  BOTTOM w0.089: JP3.2 16.31,31.52 16.18,31.64 14.78,31.64 14.4,32.02 14.4,32.49 14.28,32.62 14.28,33.81 14.03,34.06 13.57,34.06 13.29,33.77 JX3.58
UNNAMED_4_CN100PODDEVEN_I16_N5: length 6.8
  BOTTOM w0.089: JP4.2 16.31,31.99 16.18,31.86 14.87,31.86 14.62,32.11 14.62,32.58 14.49,32.71 14.49,33.9 14.12,34.27 13.51,34.27 13.21,34.57 JX3.60
UNNAMED_4_CN100PODDEVEN_I17_N4: length 4.9
  BOTTOM w0.089: JP1.2 4.62,33.25 4.79,33.42 6.22,33.42 6.85,34.06 7.04,34.06 7.32,33.77 JX3.57
UNNAMED_4_CN100PODDEVEN_I17_N5: length 4.8
  BOTTOM w0.089: JX3.59 7.34,34.57 7.04,34.27 6.76,34.27 6.13,33.64 4.75,33.64 4.62,33.76 JP2.2
UNNAMED_5_ICMT41K256M16_I195_ZQ: length 3.1
  TOP w0.14: R165.1 55.81,24.73 56.13,25.05 v1(56.19,25.05)
  BOTTOM w0.14: v1(56.19,25.05) 56.13,25.05 U2.L8
UNNAMED_5_ICMT41K256M16_I196_ZQ: length 7
  BOTTOM w0.14: R166.1 59.36,45.83 57.84,44.3 57.84,42.4 57.33,41.89 56.44,41.89 56.3,41.75 v1(56.14,41.75) 56.07,41.75 U3.L8
UNNAMED_5_ICTPS51206_I120_S3: length 3.4
  BOTTOM w0.14: U14.7 45.37,59.02 45.14,58.78 45.14,58.67 44.86,58.4 43.49,58.4 43.36,58.53 R222.2
UNNAMED_5_ICTPS51206_I120_S5: length 1.9
  BOTTOM w0.14: R221.2 45.16,59.82 U14.9
UNNAMED_5_ICTPS51206_I120_VLDOI: length 2
  BOTTOM w0.203: R6.2 48.46,59.82 U14.2
UNNAMED_5_ICTPS51206_I120_VTTSN: length 1.9
  BOTTOM w0.14: R161.2 48.57,58.27 48.22,58.62 U14.5
UNNAMED_5_ICXC7Z035_I146_PSDD_1: length 14.7
  TOP w0.14: U1.W21 v1(28.22,22.59)
  L4_SIG w0.095: v1(19.61,27.41) 20.12,27.41 20.75,28.05 21.16,28.05 21.56,28.45 21.56,28.47 22.15,29.06 23.42,29.06 23.88,28.61 23.88,26.45 27.07,23.25 27.08,23.25 27.23,23.1 27.71,23.1 v1(28.22,22.59)
  BOTTOM w0.14: R135.1 v1(19.61,27.41)
UNNAMED_5_ICXC7Z035_I146_PSDDRV: length 13.5
  TOP w0.14: U1.V21 v1(29.22,22.59)
  L17_SIG w0.095: v1(29.22,22.59) 28.83,22.21 26.34,22.21 21.38,17.25 21.07,17.25 20.94,17.38 v1(19.86,17.38)
  BOTTOM w0.14: R134.1 19.48,17 v1(19.86,17.38)
UNNAMED_6_CAP_I20_N1: length 49.4
  TOP w0.14: 51.36,23.35 51.11,23.1 50.21,23.1 v1(49.79,23.51) ; 51.36,23.35 C178.1 ; 51.36,23.35 L12.2 ; U1.M18 v1(36.22,25.59)
  L14_SIG w0.095: v1(49.79,23.51) 49.07,24.24 38.15,24.24 38.14,24.25 38.07,24.25 37.88,24.45 37.88,24.73 37.48,25.13 36.76,25.13 36.29,25.59 v1(36.22,25.59)
  L18_SIG w0.095: v1(48.69,16.36) 48.69,14.71 47.93,13.95 47.93,12.43 44.54,9.04 44.54,4.26 44.76,4.05 45.43,4.05 45.65,4.26 47.72,4.26 48.21,3.77 49.81,3.77 v1(50.73,4.68)
  BOTTOM w0.14: v1(48.69,16.36) 48.69,22.97 49.24,23.51 v1(49.79,23.51) ; v1(50.73,4.68) 51.3,4.11 C251.1
UNNAMED_6_CAP_I222_N1: length 30.1
  TOP w0.14: E1.2 28.06,48.18 28.88,47.35 C189.1 C190.1 32.06,46.72 v1(32.18,46.59) ; U1.M14 v1(36.22,29.59)
  L15_SIG w0.095: v1(36.22,29.59) 35.72,30.08 32.95,30.08 32.55,29.69 32.55,29.45 32.36,29.25 32,29.25 31.55,29.69 31.55,29.73 31.36,29.93 31.32,29.93 29.88,31.37 29.88,43.77 31.08,44.98 31.08,45.08 31.28,45.28 31.38,45.28 32.18,46.08 v1(32.18,46.59)
UNNAMED_6_CAP_I222_N2: length 33
  TOP w0.203: U1.N13 v1(35.22,31.59) ; U1.M13 v1(36.22,31.59)
  TOP w0.305: U1.M13 U1.N13 U1.P14 ; C190.2 C189.2 29.9,49.51 v1(29.77,49.64) 29.77,50.02 29.33,50.46 E12.2
  L18_SIG w0.254: v1(29.77,49.64) 29.77,47.73 32.06,45.45 32.06,44.69 32.69,44.05 33.45,44.05 33.96,43.54 33.96,39.61 33.45,39.1 33.05,39.1 32.8,38.84 32.8,38.57 32.24,38.01 32.04,38.01 31.8,37.76 31.8,37.57 31.8,37.57 31.8,35.41 32.04,35.17 32.05,35.17 32.18,35.03 33.71,35.03 33.96,34.78 33.96,33.51 34.72,32.75 34.72,32.08 v1(35.22,31.59) v1(36.22,31.59)
UNNAMED_6_DIOLED_I280_N: length 1.8
  TOP w0.14: D4.C R172.1
UNNAMED_6_ICXC7Z035_I180_CFGBVS: length 12.4
  TOP w0.14: U1.T7 v1(31.22,37.59) ; R167.2 34.09,46.59 v1(33.83,46.34)
  L15_SIG w0.095: v1(31.22,37.59) 30.66,38.14 30.66,43.67 33.33,46.34 v1(33.83,46.34)
UNNAMED_6_ICXC7Z035_I180_PROGRA: length 0.7
  TOP w0.14: U1.V9 v1(29.22,35.59)
UNNAMED_7_CAP_I123_N2: length 1
  TOP w0.14: U1.R6 v1(32.22,38.59)
  BOTTOM w0.14: C47.2 32.37,38.43 v1(32.22,38.59)
UNNAMED_7_CAP_I124_N2: length 0.7
  TOP w0.14: U1.U5 v1(30.22,39.59)
UNNAMED_7_CAP_I125_N2: length 1
  TOP w0.14: U1.R5 v1(32.22,39.59)
  BOTTOM w0.14: v1(32.22,39.59) 32.37,39.43 C45.2
UNNAMED_7_CAP_I126_N2: length 0.7
  TOP w0.14: U1.U6 v1(30.22,38.59)
UNNAMED_7_ICXC7Z035_I94_MGTRREF: length 6.6
  TOP w0.14: U1.AB8 v1(25.22,36.59)
  L17_SIG w0.095: v1(25.22,36.59) 25.22,36.57 24.69,36.05 21.13,36.05 20.88,36.3 v1(20.37,36.3)
  BOTTOM w0.14: R10.2 v1(20.37,36.3)
UNNAMED_8_AD9361_I22_RBIAS: length 0.9
  TOP w0.14: v6(67.6,33.69) U17.L4
  BOTTOM w0.14: v6(67.6,33.69) 67.46,33.83 R125.1
UNNAMED_8_AD9361_I22_RXVCOLDOOU: length 3.4
  TOP w0.14: U17.G2 v6(69.2,30.49) v6(68.4,30.49) U17.G3
  BOTTOM w0.14: C13.1 69.61,30.91 v6(69.2,30.49) 69.2,30.49 R124.1
UNNAMED_8_CAP_I19_N1: length 1.2
  BOTTOM w0.14: R124.2 C12.1
UNNAMED_8_CAP_I51_N1: length 1.1
  BOTTOM w0.14: C105.1 62.35,25 R123.2
UNNAMED_8_CAP_I135_N1: length 8.9
  TOP w0.089: C8.1 70.84,36.4 70.96,36.52 71.08,36.52 71.34,36.77 71.72,36.77 72.1,37.16 72.1,37.24 72.1,39.44 73.62,40.96 74.31,40.96 74.6,41.26 74.6,41.51 75.24,42.15 T1.6
UNNAMED_8_CAP_I136_N1: length 8.9
  TOP w0.089: T1.4 75.24,39.61 74.6,40.24 74.6,40.49 74.35,40.75 73.71,40.75 72.32,39.35 72.32,37.33 72.32,37.07 71.81,36.56 71.43,36.56 71.3,36.43 71.3,36.3 71.43,36.18 71.43,36.05 71.3,35.92 71.17,35.92 C9.1
UNNAMED_8_CAP_I137_N1: length 9.3
  TOP w0.089: C10.1 71.84,23.98 72.13,23.69 73.75,23.69 74.77,24.71 75.65,24.71 75.91,24.96 77.36,24.96 77.74,24.58 77.74,24.11 77.87,23.98 78.28,23.98 78.92,23.35 T3.6
UNNAMED_8_CAP_I138_N1: length 9.3
  TOP w0.089: T3.4 76.38,23.35 77.01,23.98 77.4,23.98 77.52,24.11 77.52,24.49 77.27,24.75 76,24.75 75.74,24.49 74.86,24.49 73.84,23.48 72.04,23.48 71.79,23.73 71.37,23.73 C11.1
UNNAMED_8_CAP_I199_N1: length 0.8
  TOP w0.14: R2.2 69.65,23.35 C7.1
UNNAMED_8_CAP_I200_N1: length 0.8
  TOP w0.14: R1.2 C6.1
UNNAMED_8_CAP_I209_N2: length 2.5
  TOP w0.089: C25.2 66.73,36.43 66.98,36.68 66.98,36.94 66.85,37.07 66.47,37.07 66.35,37.19 T5.6
UNNAMED_8_CAP_I210_N2: length 2.5
  TOP w0.089: 68.89,38.14 68.89,37.57 67.55,36.24 C26.2
UNNAMED_8_CAP_I220_N2: length 5.2
  TOP w0.089: C32.2 66.94,21.98 66.94,20.65 67.45,20.14 67.71,20.14 67.87,20.3 67.87,20.81 68.63,21.57 T7.6
UNNAMED_8_CAP_I221_N2: length 5.1
  TOP w0.089: T7.4 68.12,19.03 67.87,19.29 67.87,19.79 67.74,19.92 67.36,19.92 66.73,20.56 C33.2
UNNAMED_8_CAP_I263_N1: length 4.6
  TOP w0.089: C53.1 72.25,27.92 72.82,27.92 73.46,27.29 74.35,27.29 74.6,27.54 74.6,27.92 75.24,28.56 T4.6
UNNAMED_8_CAP_I264_N1: length 4.6
  TOP w0.089: T4.4 75.11,26.02 74.6,26.52 74.6,26.82 74.35,27.07 73.37,27.07 72.73,27.71 72.42,27.71 C56.1
UNNAMED_8_CAP_I265_N1: length 9.3
  TOP w0.089: T2.6 76.25,32.75 76.89,32.11 77.27,32.11 77.4,31.98 77.4,31.85 77.2,31.64 75.33,31.64 74.69,32.28 74.69,32.96 74.06,33.6 72.73,33.6 72.38,33.24 72.07,33.24 71.93,33.38 71.93,33.57 C51.1
UNNAMED_8_CAP_I266_N1: length 9.3
  TOP w0.089: C52.1 72.12,33 72.44,33 72.64,33.2 72.82,33.38 73.97,33.38 74.47,32.87 74.47,32.19 75.24,31.43 77.29,31.43 77.65,31.79 77.65,31.99 77.78,32.11 78.16,32.11 78.79,32.75 T2.4
UNNAMED_8_CAP_I272_N2: length 9.8
  TOP w0.089: C29.2 61.27,36.51 61.36,36.6 61.45,36.6 61.54,36.69 61.54,37.08 61.9,37.45 64.95,37.45 65.46,37.95 65.46,39.73 65.2,39.99 64.95,39.99 64.7,39.73 64.7,39.35 64.06,38.72 T6.6
UNNAMED_8_CAP_I273_N2: length 9.8
  TOP w0.089: T6.4 64.06,41.26 65.11,40.2 65.29,40.2 65.67,39.82 65.67,37.86 65.04,37.23 61.99,37.23 61.76,36.99 61.76,36.69 61.84,36.6 61.94,36.6 62.03,36.51 C30.2
UNNAMED_8_CAP_I284_N2: length 2.7
  TOP w0.089: C35.2 62.58,23.54 62.83,23.29 62.83,23.22 62.79,23.22 62.66,23.1 61.85,23.1 61.65,22.89 T8.4
UNNAMED_8_CAP_I285_N2: length 2.6
  TOP w0.089: T8.6 64.06,22.14 64.06,22.88 63.97,22.97 63.41,22.97 63.37,23.01 63.17,23.01 63.04,23.14 63.04,23.35 63.23,23.54 C34.2
UNNAMED_8_CNBNC3P_I244_CNTR: length 17.2
  TOP w0.33: T1.3 79.94,39.61 arc(80.18,39.65) 80.39,39.79 80.99,40.4 arc(81.38,40.66) 81.84,40.75 82.75,40.75 arc(83.08,40.81) 83.36,41 83.55,41.19 83.6,41.24 arc(83.9,41.44) 84.25,41.51 85.76,41.51 arc(86.01,41.46) 86.22,41.32 86.35,41.19 arc(86.56,41.05) 86.81,41 87.94,41 arc(88.52,40.89) 89.02,40.55 89.27,40.3 arc(89.76,39.97) 90.34,39.86 RX1A.1
UNNAMED_8_CNBNC3P_I245_CNTR: length 15.5
  TOP w0.33: T3.3 76.38,20.68 arc(76.49,20.95) 76.76,21.06 79.05,21.06 arc(79.28,21.02) 79.48,20.88 79.6,20.77 arc(79.81,20.62) 80.06,20.57 81.85,20.57 arc(82.28,20.66) 82.64,20.9 83.72,21.98 arc(84.53,22.52) 85.49,22.71 RX2A.1
UNNAMED_8_CNBNC3P_I246_CNTR: length 29.2
  TOP w0.33: 68.89,41.32 68.89,41.76 arc(69.05,42.59) 69.52,43.29 70.61,44.38 arc(72.5,45.64) 74.73,46.08 76.78,46.08 arc(77.11,46.15) 77.4,46.34 arc(77.68,46.52) 78.01,46.59 86.86,46.59 arc(87.85,46.79) 88.7,47.35 89.08,47.73 arc(90.2,48.49) 91.53,48.75 TX1A.1
UNNAMED_8_CNBNC3P_I247_CNTR: length 20.2
  TOP w0.33: T7.3 73.46,19.03 arc(74.05,18.92) 74.54,18.59 75.24,17.89 arc(75.42,17.61) 75.49,17.28 75.49,16.62 arc(75.88,15.67) 76.84,15.27 84.89,15.27 arc(85.54,15.14) 86.1,14.77 86.16,14.71 arc(87.14,14.06) 88.3,13.82 TX2A.1
UNNAMED_8_CNBNC3P_I254_CNTR: length 12
  TOP w0.33: T2.3 78.79,35.67 78.92,35.54 81.59,35.54 arc(81.82,35.49) 82.02,35.36 arc(82.24,35.21) 82.51,35.16 88.03,35.16 arc(88.22,35.2) 88.38,35.3 arc(88.5,35.39) 88.65,35.41 RX1B.1
UNNAMED_8_CNBNC3P_I261_CNTR: length 16.4
  TOP w0.33: T4.3 79.3,26.02 79.62,26.33 arc(79.83,26.47) 80.08,26.52 81.14,26.52 arc(81.55,26.61) 81.9,26.84 arc(82.11,26.98) 82.36,27.03 94.8,27.03 RX2B.1
UNNAMED_8_CNBNC3P_I278_CNTR: length 33.8
  TOP w0.33: TX1B.1 89.21,52.56 arc(88.08,51.81) 86.76,51.54 80.57,51.54 arc(79.98,51.43) 79.49,51.09 arc(79.26,50.82) 79.09,50.51 arc(79.02,50.2) 78.85,49.94 76.78,47.88 arc(75.78,47.21) 74.6,46.97 70.79,46.97 arc(67.74,46.36) 65.15,44.64 64.44,43.92 63.19,42.67 arc(62.89,42.47) 62.54,42.4 arc(62.07,42.31) 61.67,42.04 60.89,41.26 T6.3
UNNAMED_8_CNBNC3P_I290_CNTR: length 40.3
  TOP w0.33: TX2B.1 92.25,9.38 arc(88.38,10.15) 85.1,12.34 84.25,13.2 arc(83.55,13.66) 82.73,13.82 76.69,13.82 arc(75.82,14) 75.08,14.49 74.18,15.39 arc(73.38,15.92) 72.44,16.11 65.68,16.11 arc(65.4,16.17) 65.16,16.32 arc(65.05,16.49) 65.01,16.68 65.01,19.73 arc(64.85,20.13) 64.44,20.3 62.16,20.3 arc(61.8,20.15) 61.65,19.79 T8.3
UNNAMED_8_CNBNC3P_I292_CNTR: length 22.2
  TOP w0.33: TXM1.1 83.4,44.3 arc(82.9,44.4) 82.48,44.69 82.03,45.13 arc(81.54,45.46) 80.96,45.57 79.57,45.57 arc(79.32,45.52) 79.11,45.38 arc(78.9,45.24) 78.65,45.19 77.26,45.19 arc(76.68,45.08) 76.19,44.75 74.17,42.73 arc(73.38,42.2) 72.46,42.02 arc(72.21,41.97) 72,41.83 71.93,41.76 arc(71.7,41.41) 71.62,41 R101.1 71.55,40.05 R1.1
UNNAMED_8_CNBNC3P_I294_CNTR: length 26.4
  TOP w0.33: TXM2.1 v1(83.05,18.27)
  L2_GND w0.14: v1(83.05,18.27) 76.38,18.27 71.93,22.71 71.3,22.71 v1(70.66,23.35)
UNNAMED_8_ICFXL4T245_I328_T: length 2.2
  TOP w0.14: v1(58.73,32.91) 58.73,32.87 58.33,32.48 U22.6
  BOTTOM w0.14: R59.1 59.69,33.46 59.15,32.91 v1(58.73,32.91)
UNNAMED_9_ADP238X_I1088_BST: length 1.1
  TOP w0.14: U18.15 22.66,3.34 C253.2
UNNAMED_9_ADP238X_I1088_COMP: length 2
  TOP w0.14: U18.1 24.16,9.11 24.5,9.44 C256.1 C255.1
UNNAMED_9_ADP238X_I1088_RT: length 1.9
  TOP w0.14: U18.22 26.46,6.71 R78.1
UNNAMED_9_ADP238X_I1088_SS: length 13.7
  TOP w0.14: v1(26.47,8.11) 26.07,7.71 U18.24
  L3_SIG w0.095: v1(32.69,0.74) 32.18,1.25 32.18,2.65 31.55,3.28 29.52,3.28 28.5,4.3 28.5,4.93 26.85,6.59 26.85,7.73 v1(26.47,8.11)
  BOTTOM w0.14: C252.1 32.69,1.59 v1(32.69,0.74)
UNNAMED_9_ADP238X_I1088_SW1: length 9.7
  TOP w0.102: U18.PAD2 22.04,7.23 v2(22.4,7.6)
  TOP w0.305: C253.1 22.16,3.36 U18.14 22.16,6.33 U18.PAD2 ; U18.7 21.64,7.71 21.66,7.73 ; U18.PAD2 22.16,6.58 U18.5 ; U18.PAD2 21.66,6.83 21.66,7.73 ; 21.66,7.73 U18.6
  vias: v2(21.64,7.6) v2(21.64,7.35) v2(21.64,7.09) v2(21.64,6.84) v2(21.64,6.59) v2(21.64,6.33) v2(21.64,6.08) v2(21.64,5.82) v2(21.64,5.57) v2(21.64,5.32) v2(22.4,7.35) v2(22.4,7.09) v2(22.4,6.84) v2(22.4,6.59) v2(22.4,6.33) v2(22.4,6.08) v2(22.4,5.82) v2(22.4,5.57) v2(22.4,5.32) v3(22.02,7.6) v3(22.02,7.22) v3(22.02,6.84) v3(22.02,6.46) v3(22.02,6.08) v3(22.02,5.7) v3(22.02,5.32)
UNNAMED_9_ADP238X_I1088_VREG: length 11.9
  TOP w0.14: v2(23.17,9) 23.16,8.99 U18.3
  L2_GND w0.203: v3(23.17,8.57) v2(23.17,9)
  L17_SIG w0.095: v3(23.17,8.57) 23.17,8.49 25.33,6.33 25.33,3.46 25.11,3.25 25.11,2.97 25.33,2.75 25.33,2.27 25.96,1.63 v1(27.74,1.63)
  BOTTOM w0.14: C254.1 v1(27.74,1.63)
UNNAMED_9_ADP1754_I1076_SS: length 2.2
  TOP w0.14: U19.7 71.37,9.07 71.93,9.63 71.93,10.33 C311.1
UNNAMED_9_ADP1754_I1077_SS: length 1.5
  TOP w0.14: C340.1 81.96,9.07 U20.7
UNNAMED_9_CAP_I1113_N2: length 1.9
  TOP w0.508: C257.2 12.46,1.12 R80.1
UNNAMED_9_CAP_I1135_N2: length 0.7
  TOP w0.14: C255.2 25.82,9.81 25.9,9.82 R79.1
UNNAMED_9_DIOLED_I1083_N: length 1.7
  TOP w0.14: D3.C 31,56.62 31,55.01 R113.1
UNNAMED_9_RES_I987_N2: length 2.1
  TOP w0.14: 32.31,54.97 Q14.3
UNNAMED_10_AD7291_I1_AS0: length 2.1
  BOTTOM w0.14: U24.11 75.13,48.19 R65.2 R66.1
UNNAMED_10_AD7291_I1_AS1: length 2.1
  BOTTOM w0.14: U24.13 76.13,48.18 R63.2 R64.1
UNNAMED_10_AD7291_I1_DCAP: length 1.3
  BOTTOM w0.14: U24.8 C133.1
UNNAMED_10_AD7291_I1_VIN3: length 2.3
  BOTTOM w0.14: R67.2 R68.1 77.13,41.84 U24.1
UNNAMED_10_AD7291_I1_VIN6: length 2.2
  BOTTOM w0.14: U24.4 75.63,42.24 75.58,42.19 75.58,41.54 R62.1 R61.2
UNNAMED_10_AD7291_I1_VREF: length 2.2
  BOTTOM w0.14: U24.7 73.59,44.44 73.2,44.05 72.99,44.05 C158.1
UNNAMED_10_ADG772_I61_D1: length 45.4
  TOP w0.14: U5.2 78.08,56.3 77.75,55.96 75.34,55.96 v1(73.97,54.59)
  L7_SIG w0.095: v1(73.97,54.59) 73.08,55.48 72.44,55.48 71.62,56.31 71.62,57.19 71.43,57.39 70.16,57.39 69.52,56.75 65.71,56.75 64.44,58.02 63.81,58.02 63.43,57.64 63.43,56.37 63.93,55.86 64.57,55.86 65.33,55.1 65.33,53.8 65.18,53.65 65.18,49.5 65.33,49.35 65.33,47.35 64.06,46.08 61.65,46.08 61.14,45.57 61.14,42.53 60.89,42.27 60.89,37.83 60.38,37.32 v1(60.38,36.68)
  BOTTOM w0.14: v1(60.38,36.68) 59.89,37.17 C216.1
UNNAMED_10_ADG772_I61_IN1: length 3.3
  TOP w0.14: U5.4 80.49,57.11 R33.2 80.63,57.26 Q6.3
UNNAMED_10_ADG772_I61_S1B: length 4.6
  TOP w0.14: Y4.3 75.68,54.84 76.46,55.61 78.11,55.61 78.48,55.99 U5.3
UNNAMED_10_ADM7160_I78_VOUT: length 10.1
  TOP w0.14: v1(74.86,52.43) 74.86,52.18 74.54,51.86 C113.1 74.22,50.53 73.93,50.24 C5.1
  TOP w0.381: v1(74.86,52.43) 75.25,52.43 Y4.4
  BOTTOM w0.381: R55.1 75.24,52.05 v1(74.86,52.43) 77.9,52.43 78.6,53.13 U8.5
UNNAMED_10_CN10PAB_I48_N5A: length 9.3
  BOTTOM w0.381: P1.A5 89.64,45.07 98.17,45.07 P1.B5
UNNAMED_10_DIOLED_I52_N: length 2.7
  BOTTOM w0.14: DS1.C R75.1
UNNAMED_10_RES_I53_N2: length 3.4
  TOP w0.14: v1(77.27,50.57) 77.27,51.54 77.34,51.75 Y4.1
  BOTTOM w0.14: R55.2 R54.2 77.18,50.65 v1(77.27,50.57)
USB_ID: length 25.8
  TOP w0.14: U15.23 v1(19.63,51.69)
  L3_SIG w0.095: v1(19.63,51.69) 19.63,47.12 18.09,45.57 18.09,39.35 17.32,38.59 17.32,37.45 16.44,36.56 11.99,36.56 11.52,36.09 10.71,36.09 10.62,36.18 9.45,36.18 v1(9.45,36.17)
  BOTTOM w0.14: JX3.63 v1(9.45,36.17)
USB_OTG_CPEN: length 20.5
  TOP w0.14: U15.17 v1(19,54.69)
  L3_SIG w0.095: v3(14.02,38.46) 14.15,38.59 14.19,38.59 14.78,39.18 14.78,39.86 15.8,40.88 15.8,44.2 16.08,44.48 16.08,51.76 v1(19,54.69)
  L19_GND w0.203: v3(14.02,38.46) 13.91,38.57 v4(13.39,38.57)
USB_OTG_N: length 32.1
  TOP w0.089: 16.5,52.62 16.77,52.89 18.09,52.89 19.03,53.83 19.76,53.83 19.9,53.69 U15.19 ; 16.5,52.62 U16.6 ; 16.5,52.62 16.5,52.63 16.24,52.88 14.97,52.88 14.63,52.53 14.17,52.53 13.34,51.71 9.49,51.71 8.73,52.47 8.35,52.47 v1(8.31,52.43)
  L3_SIG w0.089: v1(8.31,52.43) 8.56,52.43 8.69,52.31 8.69,39.48 7.55,38.34 7.42,38.34 7.29,38.46 7.16,38.46 7.04,38.34 6.91,38.34 v1(6.66,38.59)
  BOTTOM w0.089: JX3.69 7.4,38.57 7.13,38.3 6.95,38.3 v1(6.66,38.59)
USB_OTG_P: length 32.2
  TOP w0.089: v1(8.69,52.81) 9.58,51.92 13.25,51.92 14.08,52.75 14.54,52.75 14.89,53.09 16.21,53.09 16.5,53.38 16.5,53.39 ; U15.18 19.9,54.19 19.76,54.05 18.94,54.05 18,53.11 16.78,53.11 16.5,53.39 ; 16.5,53.39 U16.1
  L3_SIG w0.089: v1(6.66,38.08) 7.65,38.08 8.94,39.37 8.94,52.56 v1(8.69,52.81)
  BOTTOM w0.089: JX3.67 7.35,37.77 7.04,38.08 v1(6.66,38.08)
USB_VBUS_OTG: length 19.7
  TOP w0.14: v1(19.61,52.31) 19.73,52.19 U15.22
  L3_SIG w0.095: v3(14.02,37.95) 14.53,38.46 14.66,38.46 15.17,38.97 16.69,38.97 17.2,39.48 17.2,50.65 18.85,52.31 v1(19.61,52.31)
  L19_GND w0.203: v3(14.02,37.95) 13.84,37.77 v4(13.39,37.77)
V_0_N: length 39.5
  TOP w0.14: U1.P13 v1(33.22,31.59)
  L18_SIG w0.095: v1(33.22,31.59) 32.6,30.97 27.61,30.97 26.72,30.08 26.72,27.54 26.11,26.93 26.07,26.93 25.88,26.73 25.88,26.69 25.33,26.14 23.29,26.14 23.08,25.93 23.07,25.93 22.88,25.73 22.88,25.73 22.66,25.51 22.66,25.25 22.4,25 21.01,25 20.63,24.62 20.63,24.24 20.12,23.73 20.12,19.54 19.23,18.65 19.23,18.27 18.09,17.13 14.66,17.13 14.53,17.25 13.51,17.25 10.85,14.59 10.34,14.59 9.7,13.95 v1(9.7,12.17)
  BOTTOM w0.14: JX3.3 v1(9.7,12.17)
V_0_P: length 41.7
  TOP w0.14: U1.N14 v1(35.22,29.59)
  L18_SIG w0.095: v1(10.09,11.67) 11.48,11.67 11.8,11.98 11.8,14.01 13.13,15.35 15.79,15.35 16.44,16 16.44,16.24 17.07,16.87 18.57,16.87 20.5,18.81 20.5,22.71 20.75,22.97 20.75,23.73 21.01,23.98 22.09,23.98 23.55,25.45 23.88,25.45 24.07,25.25 24.36,25.25 24.55,25.45 24.88,25.45 25.07,25.25 25.45,25.25 25.71,25.51 25.71,25.64 26.32,26.25 26.36,26.25 27.74,27.63 27.74,29.95 27.99,30.21 34.6,30.21 v1(35.22,29.59)
  BOTTOM w0.14: JX3.1 9.79,11.37 v1(10.09,11.67)
VH: length 75.2
  TOP w0.14: 58.85,50.91 57.2,50.91
  TOP w0.203: v1(62.03,45.7) 62.03,46.41 61.37,47.07 61.37,47.07 61.01,47.43 61.01,48.75 61.14,48.88 61.14,50.27 60.5,50.91 58.85,50.91 58.79,50.97 U23.3 ; U23.1 56.89,51.48 57.2,51.16 57.2,50.06 C247.1
  TOP w0.254: U7.10 v2(12.63,39.78)
  L2_GND w0.406: v2(12.63,39.78) 14.12,39.78 14.53,40.18 v3(14.53,40.49)
  L6_SIG w0.203: v1(62.03,45.7) 58.73,45.7 57.71,44.69 57.38,44.69 57.37,44.67 57.04,44.67 57.03,44.69 49.96,44.69 49.96,44.69 49.63,44.69 49.63,44.69 47.93,44.69 47.17,45.45 39.04,45.45 38.79,45.19 38.79,43.54 38.41,43.17 38.16,43.17 37.63,42.64 37.63,42.41 37.2,41.98 37.05,41.98 36.82,41.75 36.82,41.6 36.2,40.98 36.05,40.98 35.82,40.75 35.82,40.6 35.2,39.98 35.05,39.98 33.82,38.75 33.82,38.6 33.2,37.98 33.05,37.98 32.82,37.75 32.82,37.6 32.2,36.98 32.05,36.98 31.82,36.75 31.82,36.6 31.2,35.98 31.05,35.98 30.82,35.75 30.82,35.6 30.25,35.03 19.99,35.03 16.94,38.08 16.94,39.73 16.18,40.49 v3(14.53,40.49)
  BOTTOM w0.254: D1.3 v1(62.03,45.7)
VTT_0P75: length 43.2
  TOP w0.254: R147.2 54.24,40.56 v2(54.36,40.67) R149.2 ; R152.2 v1(48.95,42.02) ; R156.2 52.44,40.3 v1(52.38,40.37) ; R163.2 v1(49.46,40.18) R162.2
  TOP w0.305: R143.2 R145.2 R140.2 v1(57.39,47.42) ; v1(48.19,45.32) 48.44,45.07 R139.2 ; R148.2 R151.2 ; R148.2 R137.2 ; R148.2 v1(53.77,47.86) ; v1(49.46,46.97) 49.2,46.72 R141.2 ; R144.2 R146.2 R150.2 v1(52.19,47.42) ; C79.1 49.9,60.5 50.34,60.05 v1(50.34,59.67)
  TOP w0.406: R153.2 52.52,42.51 v1(52.38,42.65)
  L2_GND w0.406: v2(54.36,40.67) 52.68,40.67 v1(52.38,40.37)
  L10_POWER w0.406: v1(59.55,45) 67.3,45 68.25,45.96 72.06,45.96 75.62,42.4 76.2,42.4 v1(76.63,42.82)
  BOTTOM w0.203: R161.1 49.33,59.42
  BOTTOM w0.254: U24.2 v1(76.63,42.82) ; 49.33,59.42 U14.3 ; v1(59.55,45) 59.74,44.81 59.74,43.67 59.49,43.42 59.49,43.03 59.74,42.78 R160.2
  BOTTOM w0.508: R161.1 50.09,59.54 50.22,59.67 v1(50.34,59.67) 50.47,59.67 50.6,59.54 C80.1 v1(51.74,59.54) ; C101.1 52.12,47.48 v1(52.19,47.42)
  vias: v1(52.38,44.18) v1(52.38,43.42) v1(52.38,41.89) v1(52.38,41.13)
VTTVREF: length 129.8
  TOP w0.14: U1.K21 v1(38.22,22.59) ; U1.M21 v1(36.22,22.59) ; C102.1 49.61,38.68 v1(49.79,38.68)
  TOP w0.203: C123.2 56.3,25.81 56.19,25.91 v1(56.19,25.98) ; v2(55.42,42.37) 55.53,42.27 C122.2
  TOP w0.305: v1(49.79,21.91) 49.64,21.76 C103.1
  TOP w0.508: C81.1 46.03,58.59 v1(46.34,58.27)
  L2_GND w0.203: v3(57.2,42.22) 55.86,42.22 55.7,42.37 v2(55.42,42.37)
  L4_SIG w0.102: 56.19,25.91 v1(56.19,25.98) ; 56.6,23.51 55.67,22.58 55.04,22.58 54.79,22.33 ; v1(49.79,21.91) 49.8,21.91
  L4_SIG w0.203: v3(57.2,42.22) 57.2,42.27 57.58,42.65 61.79,42.65 61.92,42.78 64.31,42.78 64.44,42.65 73.33,42.65 74.09,43.42 75.36,43.42 75.62,43.16 v1(76.13,43.16) ; 56.6,23.51 56.6,24.48 56.65,24.53 56.65,25.46 56.19,25.91 ; 54.79,22.33 51.16,22.33 51.11,22.29 50.78,22.29 50.76,22.31 50.43,22.31 50.41,22.29 50.17,22.29 49.8,21.91
  L9_POWER w0.203: v3(57.2,42.22) 55.86,42.22 55.68,42.4 54.79,42.4 53.65,41.26 53.65,39.86 53.27,39.48 50.6,39.48 49.8,38.68 v1(49.79,38.68)
  L15_SIG w0.203: v3(57.2,42.22) 57.2,41.89 57.22,41.88 57.22,41.65 57.46,41.41 57.46,37.44 56.6,36.58 56.6,34.45 56.69,34.36 56.69,33 55.3,31.6 55.3,30.08 55,29.78 55,28.09 55,28.09 55,27.41 55.23,27.18 55.53,27.18 55.8,26.91 55.8,26.49 56.13,26.16 56.13,26.04 v1(56.19,25.98)
  L15_SIG w0.305: v1(49.79,21.91) 47.59,21.91 47.42,22.08 38.72,22.08 v1(38.22,22.59) 37.77,23.03 36.66,23.03 v1(36.22,22.59)
  L18_SIG w0.203: v1(76.13,43.16) 75.36,43.92 75.36,48.24 76,48.88 76,49.46 76.01,49.48 76.01,49.8 76,49.81 76,50.78 76.76,51.54 76.76,53.83 75.11,55.48 73.2,55.48 72.57,54.85 70.92,54.85 70.03,55.73 52.38,55.73 49.71,58.4 47.34,58.4 47.33,58.39 46.46,58.39 v1(46.34,58.27)
  L19_GND w0.14: v3(57.2,42.22) 56.65,42.22 v4(56.19,42.68)
  BOTTOM w0.14: U3.H1 v1(49.79,38.68) ; U2.M8 56.19,25.91 v1(56.19,25.98) ; U3.M8 v4(56.19,42.68)
  BOTTOM w0.203: U14.6 46.14,58.62 46.34,58.41 v1(46.34,58.27) C84.1 ; U2.H1 v1(49.79,21.91)
  BOTTOM w0.254: U24.3 v1(76.13,43.16)
  BOTTOM w0.305: v1(36.22,22.59) 36.31,22.49 C77.1 ; v1(38.22,22.59) 37.96,22.84 C76.1
